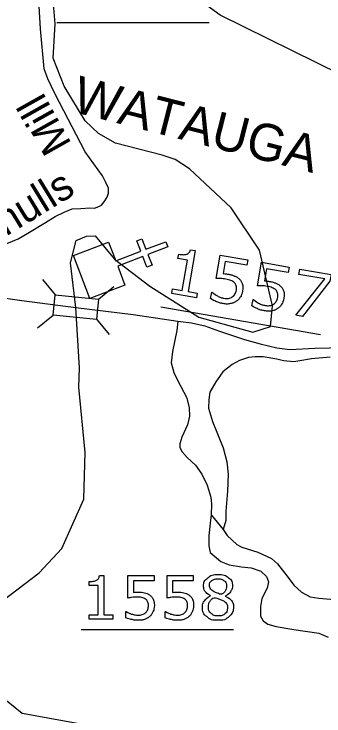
# Model space of a CAD drawing. Extents: x 1190067 to 1192950, y 891516 to 893460.
# Drawn here: x 1190885.8 to 1190916.6, y 893093.4 to 893163.2 of the extents above; entities that cross this region are included whole.
import ezdxf

# ---------------------------------------------------------------- set-up
doc = ezdxf.new("R2010")
doc.units = 0
doc.layers.add('Default', color=7, linetype='Continuous')

msp = doc.modelspace()

# ---------------------------------------------------------------- linework, layer by layer
at = {"layer": 'Default'}
for p, q in [((1190890.032, 893162.364), (1190905.194, 893162.364)), ((1190888.613, 893136.813), (1190889.87, 893135.282)), ((1190894.186, 893134.848), (1190895.717, 893136.104)), ((1190900.377, 893134.106), (1190916.264, 893131.331)), ((1190888.14, 893132.009), (1190889.671, 893133.265)), ((1190893.992, 893132.877), (1190895.249, 893131.346)), ((1190892.452, 893102.011), (1190907.614, 893102.011))]:
    msp.add_line(p, q, dxfattribs=at)
for points in [[(1190918.241, 893157.206), (1190906.289, 893163.073), (1190900.568, 893167.266), (1190897.101, 893168.428), (1190888.631, 893168.483)], [(1190911.295, 893132.126), (1190911.486, 893134.191), (1190910.193, 893139.732), (1190907.374, 893143.923), (1190903.245, 893147.798), (1190901.801, 893148.742), (1190900.515, 893149.173), (1190895.876, 893150.356), (1190894.192, 893151.31), (1190892.866, 893152.6), (1190890.784, 893156.031), (1190889.681, 893158.81), (1190889.883, 893162.225), (1190889.608, 893165.436), (1190888.631, 893168.483)], [(1190885.073, 893140.384), (1190886.196, 893140.843), (1190887.158, 893141.416), (1190888.912, 893142.471), (1190889.897, 893143.09), (1190890.791, 893143.503), (1190891.57, 893143.824), (1190892.441, 893143.87), (1190893.335, 893143.939), (1190893.793, 893143.916), (1190894.206, 893144.054), (1190894.481, 893144.214), (1190894.756, 893144.535), (1190895.054, 893144.994), (1190895.191, 893145.407), (1190895.168, 893145.888), (1190894.916, 893146.439), (1190894.572, 893147.104), (1190892.865, 893149.489), (1190889.874, 893155.223), (1190889.164, 893156.759), (1190888.797, 893157.745), (1190888.419, 893161.736), (1190888.213, 893165.13)], [(1190891.951, 893134.036), (1190891.417, 893138.462), (1190891.983, 893140.676), (1190893.011, 893141.117), (1190893.858, 893141.164), (1190895.783, 893138.846), (1190899.305, 893136.153), (1190904.173, 893133.073), (1190909.528, 893131.587), (1190911.295, 893132.126)], [(1190903.326, 893139.769), (1190903.798, 893139.686), (1190903.085, 893135.603), (1190904.01, 893135.442), (1190903.929, 893134.979)], [(1190903.929, 893134.979), (1190901.477, 893135.408), (1190901.558, 893135.87), (1190902.501, 893135.705), (1190903.031, 893138.742), (1190902.088, 893138.906), (1190902.16, 893139.32)], [(1190905.885, 893136.901), (1190906.293, 893139.235), (1190909.019, 893138.759), (1190908.926, 893138.227), (1190906.784, 893138.601), (1190906.574, 893137.396)], [(1190909.991, 893136.184), (1190910.399, 893138.518), (1190913.125, 893138.042), (1190913.032, 893137.509), (1190910.89, 893137.883), (1190910.68, 893136.679)], [(1190917.19, 893136.634), (1190914.47, 893133.138), (1190913.817, 893133.252), (1190916.691, 893136.87), (1190914.116, 893137.32), (1190914.209, 893137.853), (1190917.308, 893137.311), (1190917.19, 893136.634)], [(1190905.335, 893134.907), (1190905.447, 893135.549), (1190905.49, 893135.541)], [(1190883.778, 893135.132), (1190886.579, 893134.719), (1190891.951, 893134.036)], [(1190909.441, 893134.19), (1190909.553, 893134.832), (1190909.596, 893134.824)], [(1190883.243, 893103.848), (1190888.299, 893107.653), (1190890.556, 893110.078), (1190892.726, 893114.975), (1190892.849, 893119.626), (1190892.248, 893126.106), (1190892.307, 893128.037), (1190891.951, 893134.036)], [(1190891.951, 893134.036), (1190897.62, 893133.323), (1190902.061, 893132.662)], [(1190902.061, 893132.662), (1190901.966, 893131.741), (1190901.553, 893129.645), (1190901.426, 893128.534), (1190901.664, 893127.549), (1190902.108, 893126.66), (1190902.934, 893125.104), (1190903.187, 893124.088), (1190903.219, 893123.23), (1190903.029, 893122.373), (1190902.458, 893121.134), (1190902.267, 893120.467), (1190902.267, 893120.118), (1190902.489, 893119.673), (1190902.997, 893119.102), (1190903.838, 893118.339), (1190904.473, 893117.45), (1190904.981, 893116.37), (1190905.361, 893115.164), (1190905.425, 893114.465), (1190905.395, 893113.414), (1190905.298, 893112.591), (1190905.139, 893111.321), (1190905.171, 893110.336), (1190905.298, 893109.669), (1190905.901, 893109.13), (1190906.361, 893108.78), (1190907.186, 893108.431), (1190908.392, 893108.24), (1190909.376, 893108.145), (1190910.328, 893107.828), (1190910.899, 893107.288), (1190911.09, 893106.748), (1190910.963, 893106.113), (1190910.423, 893105.096), (1190910.296, 893104.302), (1190910.296, 893103.35), (1190910.55, 893102.873), (1190911.026, 893102.556), (1190911.835, 893102.302), (1190913.613, 893102.016), (1190916.088, 893101.666), (1190917.008, 893101.254)], [(1190902.061, 893132.662), (1190903.438, 893132.492), (1190904.744, 893132.195), (1190906.22, 893131.69), (1190908.699, 893130.843), (1190910.257, 893130.413), (1190911.904, 893130.027), (1190913.21, 893129.848), (1190915.696, 893129.967), (1190918.606, 893130.065), (1190921.603, 893130.234), (1190923.821, 893130.264)], [(1190917.217, 893129.081), (1190915.365, 893128.936), (1190914.207, 893128.733), (1190913.599, 893128.617), (1190912.587, 893128.733), (1190911.921, 893128.878), (1190910.561, 893129.11), (1190909.751, 893129.11), (1190909.085, 893129.052), (1190908.217, 893128.762), (1190907.465, 893128.357), (1190906.539, 893127.633), (1190905.844, 893126.648), (1190905.265, 893125.606), (1190905.149, 893124.882), (1190905.121, 893124.013), (1190905.526, 893122.681), (1190906.582, 893120.075), (1190906.958, 893118.685), (1190907.074, 893117.468), (1190907.016, 893115.76), (1190906.828, 893113.762), (1190906.828, 893112.835), (1190906.567, 893111.966)], [(1190905.395, 893113.414), (1190906.567, 893111.966), (1190906.987, 893111.358), (1190907.942, 893110.461), (1190908.434, 893110.2), (1190910.026, 893109.708), (1190911.386, 893109.071), (1190911.993, 893108.549), (1190913.035, 893107.188), (1190913.614, 893106.435), (1190914.366, 893105.711), (1190915.234, 893105.277), (1190916.074, 893105.132), (1190917.26, 893105.045), (1190917.926, 893104.958), (1190918.475, 893104.901), (1190918.852, 893104.756), (1190919.257, 893104.408), (1190920.183, 893102.816)], [(1190894.279, 893107.39), (1190894.732, 893107.39), (1190894.732, 893103.47), (1190895.62, 893103.47), (1190895.62, 893103.026)], [(1190897.092, 893105.135), (1190897.092, 893107.376), (1190899.709, 893107.376), (1190899.709, 893106.865), (1190897.653, 893106.865), (1190897.653, 893105.708)], [(1190900.997, 893105.135), (1190900.997, 893107.376), (1190903.614, 893107.376), (1190903.614, 893106.865), (1190901.558, 893106.865), (1190901.558, 893105.708)], [(1190895.62, 893103.026), (1190893.266, 893103.026), (1190893.266, 893103.47), (1190894.171, 893103.47), (1190894.171, 893106.385), (1190893.266, 893106.385), (1190893.266, 893106.783)], [(1190905.326, 893105.349), (1190905.326, 893105.366)], [(1190906.772, 893105.343), (1190906.772, 893105.325)], [(1190895.072, 893071.995), (1190895.16, 893075.059), (1190894.6, 893076.104), (1190894.67, 893079.031), (1190895.44, 893080.279), (1190898.888, 893083.889), (1190899.483, 893089.391), (1190898.205, 893090.91), (1190892.99, 893092.508), (1190886.601, 893093.67), (1190884.328, 893095.497), (1190882.665, 893099.205), (1190883.243, 893103.848)], [(1190896.904, 893103.188), (1190896.904, 893103.804), (1190896.945, 893103.804)], [(1190900.809, 893103.188), (1190900.809, 893103.804), (1190900.849, 893103.804)]]:
    msp.add_lwpolyline(points, dxfattribs=at)
for points in [[(1190895.18, 893140.524), (1190895.896, 893138.664), (1190898.385, 893139.617), (1190897.984, 893140.663), (1190898.506, 893140.863), (1190898.907, 893139.817), (1190900.872, 893140.57), (1190901.073, 893140.046), (1190899.107, 893139.293), (1190899.508, 893138.248), (1190898.986, 893138.048), (1190898.585, 893139.093), (1190896.096, 893138.14), (1190896.815, 893136.255), (1190893.335, 893134.922), (1190891.7, 893139.191)], [(1190889.87, 893135.282), (1190894.187, 893134.857), (1190893.988, 893132.84), (1190889.671, 893133.265)]]:
    msp.add_lwpolyline(points, close=True, dxfattribs=at)
for points in [[(1190902.16, 893139.32), (1190902.352, 893139.287), (1190902.577, 893139.281), (1190902.801, 893139.274), (1190902.924, 893139.315), (1190903.078, 893139.367), (1190903.179, 893139.47), (1190903.28, 893139.573), (1190903.326, 893139.769)], [(1190905.49, 893135.541), (1190905.711, 893135.339), (1190906.027, 893135.17), (1190906.342, 893135), (1190906.664, 893134.944), (1190906.88, 893134.906), (1190907.093, 893134.931), (1190907.306, 893134.957), (1190907.491, 893135.082), (1190907.648, 893135.19), (1190907.749, 893135.361), (1190907.849, 893135.532), (1190907.891, 893135.773), (1190907.932, 893136.008), (1190907.88, 893136.183), (1190907.827, 893136.359), (1190907.701, 893136.482), (1190907.564, 893136.625), (1190907.345, 893136.712), (1190907.127, 893136.799), (1190906.847, 893136.848), (1190906.58, 893136.894), (1190906.325, 893136.901), (1190906.071, 893136.907), (1190905.885, 893136.901)], [(1190906.574, 893137.396), (1190906.707, 893137.386), (1190906.845, 893137.368), (1190906.983, 893137.35), (1190907.084, 893137.332), (1190907.452, 893137.268), (1190907.718, 893137.157), (1190907.984, 893137.046), (1190908.188, 893136.848), (1190908.402, 893136.638), (1190908.49, 893136.349), (1190908.578, 893136.061), (1190908.508, 893135.662)], [(1190909.596, 893134.824), (1190909.817, 893134.622), (1190910.133, 893134.452), (1190910.448, 893134.283), (1190910.77, 893134.226), (1190910.987, 893134.189), (1190911.2, 893134.214), (1190911.413, 893134.24), (1190911.597, 893134.365), (1190911.754, 893134.473), (1190911.855, 893134.644), (1190911.955, 893134.815), (1190911.997, 893135.056), (1190912.038, 893135.291), (1190911.986, 893135.466), (1190911.933, 893135.642), (1190911.808, 893135.765), (1190911.67, 893135.908), (1190911.451, 893135.995), (1190911.233, 893136.082), (1190910.953, 893136.131), (1190910.686, 893136.177), (1190910.431, 893136.184), (1190910.177, 893136.19), (1190909.991, 893136.184)], [(1190910.68, 893136.679), (1190910.813, 893136.668), (1190910.951, 893136.651), (1190911.089, 893136.633), (1190911.19, 893136.615), (1190911.558, 893136.551), (1190911.824, 893136.44), (1190912.09, 893136.329), (1190912.294, 893136.13), (1190912.508, 893135.92), (1190912.596, 893135.632), (1190912.684, 893135.344), (1190912.614, 893134.945)], [(1190908.508, 893135.662), (1190908.453, 893135.345), (1190908.287, 893135.076), (1190908.121, 893134.807), (1190907.885, 893134.644), (1190907.629, 893134.469), (1190907.306, 893134.408), (1190906.983, 893134.347), (1190906.585, 893134.416), (1190906.214, 893134.481), (1190905.883, 893134.619), (1190905.553, 893134.756), (1190905.335, 893134.907)], [(1190912.614, 893134.945), (1190912.559, 893134.628), (1190912.393, 893134.359), (1190912.227, 893134.09), (1190911.991, 893133.927), (1190911.735, 893133.752), (1190911.412, 893133.691), (1190911.09, 893133.629), (1190910.691, 893133.699), (1190910.32, 893133.764), (1190909.989, 893133.901), (1190909.659, 893134.039), (1190909.441, 893134.19)], [(1190893.266, 893106.783), (1190893.45, 893106.783), (1190893.66, 893106.814), (1190893.87, 893106.844), (1190893.978, 893106.903), (1190894.113, 893106.976), (1190894.19, 893107.088), (1190894.268, 893107.2), (1190894.279, 893107.39)], [(1190905.326, 893105.366), (1190904.975, 893105.553), (1190904.807, 893105.775), (1190904.639, 893105.997), (1190904.639, 893106.33), (1190904.639, 893106.821), (1190905.042, 893107.148), (1190905.445, 893107.475), (1190906.068, 893107.475), (1190906.72, 893107.475), (1190907.108, 893107.163), (1190907.497, 893106.85), (1190907.497, 893106.368), (1190907.497, 893106.073), (1190907.313, 893105.788), (1190907.129, 893105.503), (1190906.772, 893105.343)], [(1190906.922, 893106.362), (1190906.922, 893106.675), (1190906.681, 893106.86), (1190906.439, 893107.046), (1190906.065, 893107.046), (1190905.696, 893107.046), (1190905.46, 893106.87), (1190905.225, 893106.695), (1190905.225, 893106.397), (1190905.225, 893106.187), (1190905.343, 893106.034), (1190905.462, 893105.88), (1190905.701, 893105.76), (1190905.81, 893105.708), (1190906.013, 893105.623), (1190906.216, 893105.538), (1190906.409, 893105.483), (1190906.699, 893105.676), (1190906.811, 893105.883), (1190906.922, 893106.091), (1190906.922, 893106.362)], [(1190897.653, 893105.708), (1190897.779, 893105.72), (1190897.911, 893105.726), (1190898.042, 893105.732), (1190898.139, 893105.732), (1190898.492, 893105.732), (1190898.758, 893105.672), (1190899.024, 893105.612), (1190899.247, 893105.46), (1190899.48, 893105.299), (1190899.609, 893105.045), (1190899.738, 893104.79), (1190899.738, 893104.407)], [(1190901.558, 893105.708), (1190901.684, 893105.72), (1190901.815, 893105.726), (1190901.947, 893105.732), (1190902.043, 893105.732), (1190902.397, 893105.732), (1190902.663, 893105.672), (1190902.929, 893105.612), (1190903.151, 893105.46), (1190903.385, 893105.299), (1190903.514, 893105.045), (1190903.642, 893104.79), (1190903.642, 893104.407)], [(1190896.945, 893103.804), (1190897.184, 893103.652), (1190897.506, 893103.545), (1190897.827, 893103.438), (1190898.137, 893103.438), (1190898.344, 893103.438), (1190898.538, 893103.496), (1190898.733, 893103.555), (1190898.885, 893103.701), (1190899.013, 893103.827), (1190899.079, 893104.003), (1190899.145, 893104.179), (1190899.145, 893104.41), (1190899.145, 893104.636), (1190899.067, 893104.791), (1190898.99, 893104.946), (1190898.853, 893105.04), (1190898.701, 893105.151), (1190898.483, 893105.196), (1190898.266, 893105.242), (1190897.997, 893105.242), (1190897.74, 893105.242), (1190897.502, 893105.206), (1190897.264, 893105.171), (1190897.092, 893105.135)], [(1190900.849, 893103.804), (1190901.089, 893103.652), (1190901.41, 893103.545), (1190901.732, 893103.438), (1190902.041, 893103.438), (1190902.249, 893103.438), (1190902.443, 893103.496), (1190902.637, 893103.555), (1190902.789, 893103.701), (1190902.918, 893103.827), (1190902.984, 893104.003), (1190903.049, 893104.179), (1190903.049, 893104.41), (1190903.049, 893104.636), (1190902.972, 893104.791), (1190902.895, 893104.946), (1190902.757, 893105.04), (1190902.606, 893105.151), (1190902.388, 893105.196), (1190902.17, 893105.242), (1190901.902, 893105.242), (1190901.645, 893105.242), (1190901.407, 893105.206), (1190901.169, 893105.171), (1190900.997, 893105.135)], [(1190907.614, 893104.238), (1190907.614, 893103.674), (1190907.174, 893103.301), (1190906.734, 893102.927), (1190906.068, 893102.927), (1190905.36, 893102.927), (1190904.941, 893103.292), (1190904.521, 893103.657), (1190904.521, 893104.227), (1190904.521, 893104.589), (1190904.732, 893104.883), (1190904.943, 893105.176), (1190905.326, 893105.349)], [(1190907.014, 893104.184), (1190907.014, 893104.452), (1190906.896, 893104.614), (1190906.777, 893104.776), (1190906.432, 893104.94), (1190906.295, 893105.004), (1190906.131, 893105.059), (1190905.967, 893105.115), (1190905.695, 893105.214), (1190905.432, 893105.071), (1190905.273, 893104.826), (1190905.115, 893104.581), (1190905.115, 893104.271), (1190905.115, 893103.877), (1190905.386, 893103.62), (1190905.658, 893103.363), (1190906.076, 893103.363), (1190906.503, 893103.363), (1190906.759, 893103.582), (1190907.014, 893103.801), (1190907.014, 893104.184)], [(1190906.772, 893105.325), (1190907.182, 893105.15), (1190907.398, 893104.893), (1190907.614, 893104.636), (1190907.614, 893104.238)], [(1190899.738, 893104.407), (1190899.738, 893104.103), (1190899.627, 893103.825), (1190899.516, 893103.548), (1190899.323, 893103.358), (1190899.113, 893103.153), (1190898.822, 893103.043), (1190898.531, 893102.934), (1190898.148, 893102.934), (1190897.792, 893102.934), (1190897.462, 893103.008), (1190897.132, 893103.083), (1190896.904, 893103.188)], [(1190903.642, 893104.407), (1190903.642, 893104.103), (1190903.531, 893103.825), (1190903.42, 893103.548), (1190903.227, 893103.358), (1190903.017, 893103.153), (1190902.726, 893103.043), (1190902.436, 893102.934), (1190902.053, 893102.934), (1190901.697, 893102.934), (1190901.367, 893103.008), (1190901.036, 893103.083), (1190900.809, 893103.188)]]:
    msp.add_open_spline(points, degree=3, dxfattribs=at)

# ---------------------------------------------------------------- texts
for s, height, rotation, p in [('WATAUGA', 3.675, 345.69466, (1190891.425, 893153.524)), ('Mill', 3, 119.31751, (1190891.564, 893150.285)), ('Shulls', 3, 31.44574, (1190882.708, 893139.671))]:
    msp.add_text(s, height=height, rotation=rotation, dxfattribs=at).set_placement(p)

doc.saveas('drawing.dxf')
